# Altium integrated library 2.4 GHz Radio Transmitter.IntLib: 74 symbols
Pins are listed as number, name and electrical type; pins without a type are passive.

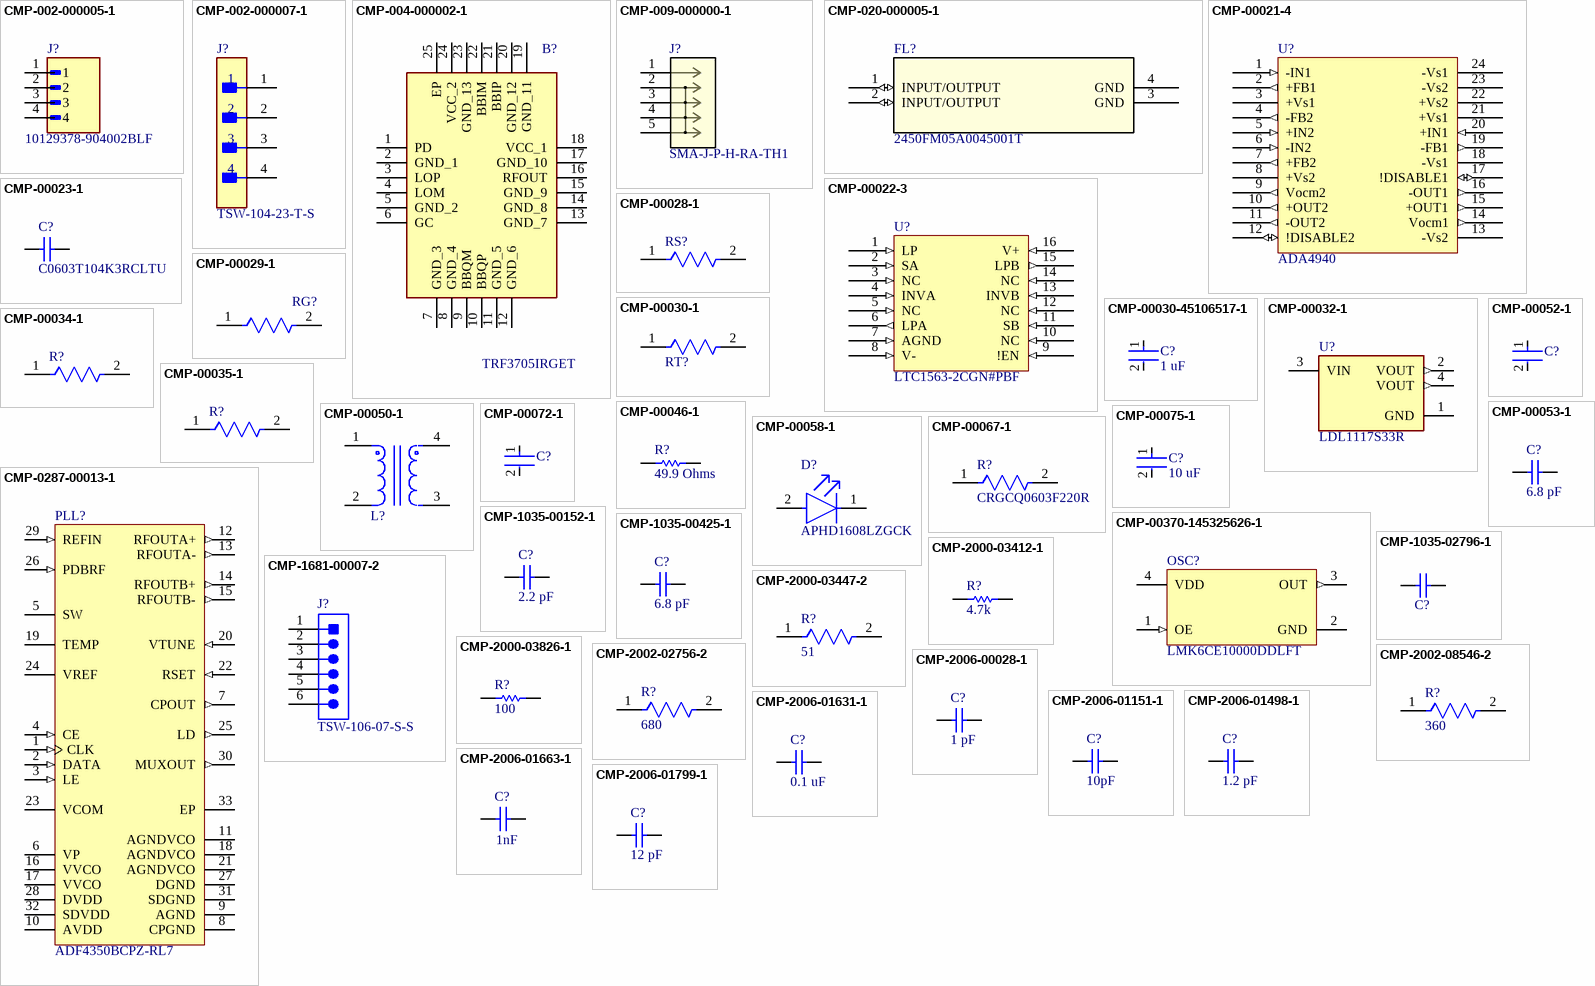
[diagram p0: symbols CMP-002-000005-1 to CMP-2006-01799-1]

## CMP-002-000005-1
designator J?, comment 10129378-904002BLF
EconoStikâ„¢ 2.54mm, Board to Board Connector, Unshrouded Verticl Header, Through Hole, Single Row, 4 Positions, 2.54 mm (0.100in) Pitch.; MF: Amphenol ICC (FCI)
footprint AMPHENOL_10129378-904002BLF
pins: 1, 2, 3, 4

## CMP-002-000007-1
designator J?, comment TSW-104-23-T-S
Pin Header, Board-to-Board, 2.54 mm, 1 Rows, 4 Contacts, Through Hole, TSW Series
footprint FP-TSW-104-23-T-S-MFG
pins: 1, 2, 3, 4

## CMP-004-000002-1
designator B?, comment TRF3705IRGET
TRF3705IRGET, Modulator Quadrature 3.1dB 3.15  3.6 V 24-Pin VQFN; Manufacturer_Name: Texas Instruments; Geometry.Height: 1mm
footprint QFN50P400X400X100-25N-D
pins: 1 PD, 2 GND_1, 3 LOP, 4 LOM, 5 GND_2, 6 GC, 7 GND_3, 8 GND_4, 9 BBQM, 10 BBQP, 11 GND_5, 12 GND_6, 13 GND_7, 14 GND_8, 15 GND_9, 16 RFOUT, 17 GND_10, 18 VCC_1, 19 GND_11, 20 GND_12, 21 BBIP, 22 BBIM, 23 GND_13, 24 VCC_2, 25 EP

## CMP-009-000000-1
designator J?, comment SMA-J-P-H-RA-TH1
Description; Manufacturer_Name: Samtec Inc
footprint CONN_SMA-J-P-H-RA-TH1_SAI
pins: 1, 2, 3, 4, 5

## CMP-020-000005-1
designator FL?, comment 2450FM05A0045001T
Description; Manufacturer_Name: Johanson Technology
footprint 2450FM05_JOT
pins: 1 INPUT/OUTPUT (io), 2 INPUT/OUTPUT (io), 3 GND (power), 4 GND (power)

## CMP-00021-4
designator U?, comment ADA4940
ROHS3Compliant EAR99 ADA4940 Tape & Reel (TR) op amp amplifier circuit 3mm 1.1muA 60muV 90dB
footprint ADA4940-Footprint-1
pins: 1 -IN1 (in), 2 +FB1 (out), 3 +Vs1 (power), 4 -FB2 (out), 5 +IN2 (in), 6 -IN2 (in), 7 +FB2 (out), 8 +Vs2 (power), 9 Vocm2 (out), 10 +OUT2 (out), 11 -OUT2 (out), 12 !DISABLE2 (io), 13 -Vs2 (power), 14 Vocm1 (out), 15 +OUT1 (out), 16 -OUT1 (out), 17 !DISABLE1 (io), 18 -Vs1 (power), 19 -FB1 (out), 20 +IN1 (in), 21 +Vs1 (power), 22 +Vs2 (power), 23 -Vs2 (power), 24 -Vs1 (power)

## CMP-00022-3
designator U?, comment LTC1563-2CGN#PBF
Active Filter Dual Low Pass 8th Order 256kHz 16-Pin SSOP N
footprint LTC1563-2CGN#PBF-Footprint-1
pins: 1 LP (in), 2 SA (in), 3 NC (in), 4 INVA (in), 5 NC (in), 6 LPA (out), 7 AGND (in), 8 V- (in), 9 !EN (in), 10 NC (in), 11 SB (in), 12 NC (in), 13 INVB (in), 14 NC (in), 15 LPB (out), 16 V+ (in)

## CMP-00023-1
designator C?, comment C0603T104K3RCLTU
Ceramic Capacitor, Multilayer, Ceramic, 25V, 10% +Tol, 10% -Tol, X7R, 15% TC, 0.1uF, Surface Mount, 0603
footprint CAPC1608X87X35LL15T15 (Chip Capacitor, 2-Leads, Body 1.60x0.80mm, IPC High Density)
footprint CAPC1608X87X35ML15T15 (Chip Capacitor, 2-Leads, Body 1.60x0.80mm, IPC Low Density)
footprint CAPC1608X87X35NL15T15 (Chip Capacitor, 2-Leads, Body 1.60x0.80mm, IPC Medium Density)
pins: 1, 2
1 alternate drawing of the same symbol

## CMP-00028-1
designator RS?, comment CRCW060350R0FKEA  (value not drawn)
Res Thick Film 0603 50 Ohm 1% 0.1W(1/10W) ±100ppm/C Pad SMD Automotive T/R
footprint FP-CRCW0603-e3-IPC_C
footprint FP-CRCW0603-e3-IPC_B
footprint FP-CRCW0603-e3-IPC_A
footprint FP-CRCW0603-e3-MFG
pins: 1, 2

## CMP-00029-1
designator RG?, comment 6-1879336-2  (value not drawn)
Fixed Resistor, Thin Film, 0.063W, 1000ohm, 50V, 1% +/-Tol, 50ppm/Cel, Surface Mount, 0603
footprint FP-CPF0603-MFG
footprint FP-CPF0603-IPC_A
footprint FP-CPF0603-IPC_B
footprint FP-CPF0603-IPC_C
pins: 1, 2

## CMP-00030-1
designator RT?, comment CR0603-FX-52R3ELF  (value not drawn)
Resistor, thick film, SMD 0603 (1608), 52.3 Ω, 0.1 W, ±1 %, CR0603-FX-52R3ELF
footprint FP-CR0603-IPC_A
footprint FP-CR0603-IPC_B
footprint FP-CR0603-MFG
footprint FP-CR0603-IPC_C
pins: 1, 2

## CMP-00030-45106517-1
designator C?, comment 1 uF
VJ0603Y105KXJCW1BC Multilayer Ceramic Capacitor, 1 uF, 16 V, ± 10%, X7R, 0603 [1608 Metric]; NexarPartId: 45106517; Capacitance: 1µF; Voltage Rating: 16V; Dielectric Material: Tantalum
footprint FP-VJ0603Y105KXJCW1BC-MFG (Multilayer Ceramic Capacitor, 1 uF, 16 V, ± 10%, X7R, 0603 [1608 Metric])
footprint FP-VJ0603Y105KXJCW1BC-IPC_A (Multilayer Ceramic Capacitor, 1 uF, 16 V, ± 10%, X7R, 0603 [1608 Metric])
footprint FP-VJ0603Y105KXJCW1BC-IPC_B (Multilayer Ceramic Capacitor, 1 uF, 16 V, ± 10%, X7R, 0603 [1608 Metric])
footprint FP-VJ0603Y105KXJCW1BC-IPC_C (Multilayer Ceramic Capacitor, 1 uF, 16 V, ± 10%, X7R, 0603 [1608 Metric])
pins: 1, 2

## CMP-00032-1
designator U?, comment LDL1117S33R
LDL1117 Series 1.2 A 3.3 V High PSRR LDO Linear Voltage Regulator-SOT-223
footprint FP-SOT223-0046067-IPC_A
footprint FP-SOT223-0046067-IPC_B
footprint FP-SOT223-0046067-IPC_C
pins: 1 GND (power), 2 VOUT (out), 3 VIN (power), 4 VOUT (out)

## CMP-00034-1
designator R?, comment CPF0603B120KE1  (value not drawn)
Res Thin Film 0603 120K Ohm 0.1% 1/16W ±25ppm/°C Molded SMD SMD Paper T/R
footprint FP-CPF0603-MFG
footprint FP-CPF0603-IPC_A
footprint FP-CPF0603-IPC_B
footprint FP-CPF0603-IPC_C
pins: 1, 2

## CMP-00035-1
designator R?, comment CRGCQ0603F22R  (value not drawn)
Res Thick Film 0603 22 Ohm 1% 0.1W(1/10W) ±200ppm/C Pad SMD Automotive T/R
footprint FP-CRGCQ0603-IPC_A
footprint FP-CRGCQ0603-IPC_C
footprint FP-CRGCQ0603-IPC_B
pins: 1, 2

## CMP-00046-1
designator R?, comment 49.9 Ohms
Res Thin Film 0603 49.9 Ohm 0.1% 1/8W ±25ppm/°C Molded SMD SMD Paper T/R; Power Rating: 125mW; Working Voltage: 75V; Max Power Dissipation: 100mW; Value: 49.9Ω; Voltage Rating (DC): 50V
footprint RESC1609X55X30NL10T20 (Chip Resistor, 2-Leads, Body 1.60x0.85mm, IPC Medium Density)
footprint RESC1609X55X30ML10T20 (Chip Resistor, 2-Leads, Body 1.60x0.85mm, IPC Low Density)
footprint RESC1609X55X30LL10T20 (Chip Resistor, 2-Leads, Body 1.60x0.85mm, IPC High Density)
pins: 1, 2
1 alternate drawing of the same symbol

## CMP-00050-1
designator L?, comment DLW5BSM501TQ2L  (value not drawn)
Common Mode Chokes Dual 500Ohm 100MHz 1A 0.23Ohm DCR SMD T/R; Tolerance: 40%; Core Material: Ferrite; Value: 500Ω; Impedance: 2.8kΩ; DC Resistance (DCR): 230mΩ; Insulation Resistance: 10MΩ; Number of Circuits: 2; Voltage Rating: 50V
footprint FP-DLW5BS-MFG
pins: 1, 2, 3, 4

## CMP-00052-1
designator C?, comment CGA5L2C0G1H104J160AA  (value not drawn)
CGA Series 1206 100 nF 50 V ±5 % Tolerance C0G SMT Multilayer Ceramic Capacitor
footprint FP-CGA5L-MFG
footprint FP-CGA5L-IPC_B
footprint FP-CGA5L-IPC_C
footprint FP-CGA5L-IPC_A
pins: 1, 2

## CMP-00053-1
designator C?, comment 6.8 pF
6.8pF 0603 C0G Multilayer Ceramic Capacitors MLCC - SMD/SMT 16volts +/-0.5pF; Voltage Rating (DC): 16V
footprint CAPC0603(1608)100_N (Chip Capacitor, Body 1.6x0.8mm, Height 1.0mm, IPC Medium Density)
footprint CAPC0603(1608)100_L (Chip Capacitor, Body 1.6x0.8mm, Height 1.0mm, IPC High Density)
footprint CAPC0603(1608)100_M (Chip Capacitor, Body 1.6x0.8mm, Height 1.0mm, IPC Low Density)
pins: 1, 2
1 alternate drawing of the same symbol

## CMP-00058-1
designator D?, comment APHD1608LZGCK
Standard LEDs; SMD 0608 Compact Dome Lens LED; 1.6x0.8 mm; Green; (Cut Reel)
footprint FP-APHD1608LZGCK-MFG
pins: 1 C, 2 A

## CMP-00067-1
designator R?, comment CRGCQ0603F220R
Res Thick Film 0603 220 Ohm 1% 0.1W(1/10W) ±100ppm/C Pad SMD T/R Automotive
footprint FP-CRGCQ0603-IPC_A
footprint FP-CRGCQ0603-IPC_C
footprint FP-CRGCQ0603-IPC_B
pins: 1, 2

## CMP-00072-1
designator C?, comment GRM21BZ71H475ME15K  (value not drawn)
Cap, Mlcc, 4.7Uf, X7R, 50V, 0805 Rohs Compliant: Yes
footprint FP-GRM21B-0_2-e0_2_0_7-IPC_A
footprint FP-GRM21B-0_2-e0_2_0_7-MFG
footprint FP-GRM21B-0_2-e0_2_0_7-IPC_C
footprint FP-GRM21B-0_2-e0_2_0_7-IPC_B
pins: 1, 2

## CMP-00075-1
designator C?, comment 10 uF
0805 10 uF 6.3 V ±10% Tolerance X7R Multilayer Ceramic Chip Capacitor; Manufacturer Lifecycle Status: IN PRODUCTION; Voltage Rating: 6.3V; Value: 10µF
footprint FP-GCM21B-0_15-IPC_A
footprint FP-GCM21B-0_15-IPC_C
footprint FP-GCM21B-0_15-MFG
footprint FP-GCM21B-0_15-IPC_B
pins: 1, 2

## CMP-0287-00013-1
designator PLL?, comment ADF4350BCPZ-RL7
Wideband Synthesizer with Integrated VCO, CP-32-2, Pb-Free, 1500 Reel; RF Prescalers: 4/5, 8/9; Single/Dual: Single; Max RF Input (MHz): 4.4GHz; Supply Current: 110mA; Frequency Range: 137.5MHz-4.35GHz; Max REFin (MHz): 250MHz; Norm Phase Noise (dBc/Hz): -220dBc
footprint ADI-CP-32-2_L (QFN, 32-Leads, Body 5x5mm, Pitch 0.5mm, Thermal Pad 3.1x3.1mm, IPC High Density)
footprint ADI-CP-32-2_M (QFN, 32-Leads, Body 5x5mm, Pitch 0.5mm, Thermal Pad 3.1x3.1mm, IPC Low Density)
footprint ADI-CP-32-2_N (QFN, 32-Leads, Body 5x5mm, Pitch 0.5mm, Thermal Pad 3.1x3.1mm, IPC Medium Density)
pins: 1 CLK (in) "Serial Clock Input. Data is clocked into the 32-bit shift register on the CLK rising edge. This input is a high impedance CMOS input.", 2 DATA (in) "Serial Data Input. The serial data is loaded MSB first with the three LSBs as the control bits. This input is a high impedance CMOS input.", 3 LE (in) "Load Enable, CMOS Input. When LE goes high, the data stored in the shift register is loaded into the register that is selected by the three LSBs.", 4 CE (in) "Chip Enable. A logic low on this pin powers down the device and puts the charge pump into three-state mode. [see datasheet]", 5 SW "Fast-Lock Switch. A connection should be made from the loop filter to this pin when using the fast-lock mode.", 6 VP (power) "Charge Pump Power Supply. This pin is to be equal to AVDD. Decoupling capacitors to the ground plane are to be placed as close as possible to this pin.", 7 CPOUT (out) "Charge Pump Output. When enabled, this provides +/-ICP to the external loop filter. The output of the loop filter is connected to VTUNE to drive the internal VCO.", 8 CPGND (power) "Charge Pump Ground. This is the ground return pin for CPOUT.", 9 AGND (power) "Analog Ground. This is a ground return pin for AVDD.", 10 AVDD (power) "Analog Power Supply. This pin ranges from 3.0 V to 3.6 V. Decoupling capacitors to the analog ground plane are to be placed as close as possible to this pin. [see datasheet]", 11 AGNDVCO (power) "VCO Analog Ground. These are the ground return pins for the VCO.", 12 RFOUTA+ (out) "VCO Output. The output level is programmable. The VCO fundamental output or a divided down version is available.", 13 RFOUTA- (out) "Complementary VCO Output. The output level is programmable. The VCO fundamental output or a divided down version is available.", 14 RFOUTB+ (out) "Auxilliary VCO Output. The output level is programmable. The VCO fundamental output or a divided down version is available.", 15 RFOUTB- (out) "Complementary Auxilliary VCO Output. The output level is programmable. The VCO fundamental output or a divided down version is available.", 16 VVCO (power) "Power Supply for the VCO. This ranges from 3.0 V to 3.6 V. Decoupling capacitors to the analog ground plane should be placed as close as possible to these pins. [see datasheet]", 17 VVCO (power) "Power Supply for the VCO. This ranges from 3.0 V to 3.6 V. Decoupling capacitors to the analog ground plane should be placed as close as possible to these pins. [see datasheet]", 18 AGNDVCO (power) "VCO Analog Ground. These are the ground return pins for the VCO.", 19 TEMP "Temperature Compensation Output. Decoupling capacitors to the ground plane are to be placed as close as possible to this pin.", 20 VTUNE (in) "Control Input to the VCO. This voltage determines the output frequency and is derived from filtering the CPOUT output voltage.", 21 AGNDVCO (power) "VCO Analog Ground. These are the ground return pins for the VCO.", 22 RSET (in) "Connecting a resistor between this pin and GND sets the charge pump output current. The nominal voltage bias at the RSET pin is 0.55 V. [see datasheet.]", 23 VCOM "Internal Compensation Node Biased at Half the Tuning Range. Decoupling capacitors to the ground plane should be placed as close as possible to this pin.", 24 VREF "Reference Voltage. Decoupling capacitors to the ground plane should be placed as close as possible to this pin.", 25 LD (out) "Lock Detect Output Pin. This pin outputs a logic high to indicate PLL lock. A logic low output indicates loss of PLL lock.", 26 PDBRF (in) "RF Power-Down. A logic low on this pin mutes the RF outputs. This function is also software controllable.", 27 DGND (power) "Digital Ground. Ground return path for DVDD.", 28 DVDD (power) "Digital Power Supply. This pin should be the same voltage as AVDD. Decoupling capacitors to the ground plane should be placed as close as possible to this pin.", 29 REFIN (in) "Reference Input. This is a CMOS input with a nominal threshold of VDD/2 and a dc equivalent input resistance of 100 k ohm. [see datasheet]", 30 MUXOUT (out) "Multiplexer Output. This multiplexer output allows either the lock detect, the scaled RF, or the scaled reference frequency to be accessed externally.", 31 SDGND (power) "Digital Sigma-Delta (Sigma-Delta) Modulator Ground. Ground return path for the Sigma-Delta modulator.", 32 SDVDD (power) "Power Supply Pin for the Digital Sigma-Delta Modulator. Should be the same voltage as AVDD. Decouplingcapacitorsto the ground plane are to be placed as close as possible to this pin.", 33 EP (power) "Exposed Pad."

## CMP-00370-145325626-1
designator OSC?, comment LMK6CE10000DDLFT
IC 100 MHz LVCMOS Oscillator 1.8V Enable/Disable 4-VDFN; Manufacturer Lifecycle Status: ACTIVE; Frequency: 100MHz; Load Capacitance: 15pF; Max Supply Current: 44mA; Max Junction Temperature (Tj): 125°C; Max Supply Voltage: 1.9V; Min Supply Voltage: 1.7V
footprint DLF0004A_MFG (Recommended Land Pattern)
footprint DFN250X200X100-4_DLF0004A_L
footprint DFN250X200X100-4_DLF0004A_M
footprint DFN250X200X100-4_DLF0004A_N
pins: 1 OE (in), 2 GND (power), 3 OUT (out), 4 VDD (power)

## CMP-1035-00152-1
designator C?, comment 2.2 pF
CAP 2.2pF 16V ±0.5pF 0603 (1608 Metric) Thickness 1mm SMD; Case-EIA: 0603; Tolerance: Â±0.5pF; Case-Metric: 1608
footprint CAPC0603(1608)100_N (Chip Capacitor, Body 1.6x0.8mm, Height 1.0mm, IPC Medium Density)
footprint CAPC0603(1608)100_M (Chip Capacitor, Body 1.6x0.8mm, Height 1.0mm, IPC Low Density)
footprint CAPC0603(1608)100_L (Chip Capacitor, Body 1.6x0.8mm, Height 1.0mm, IPC High Density)
pins: 1, 2
1 alternate drawing of the same symbol

## CMP-1035-00425-1
designator C?, comment 6.8 pF
CAP 6.8pF 16V ±0.5pF 0603 (1608 Metric) Thickness 1mm SMD; Case-Metric: 1608; Tolerance: Â±0.5pF; Case-EIA: 0603
footprint CAPC0603(1608)100_L (Chip Capacitor, Body 1.6x0.8mm, Height 1.0mm, IPC High Density)
footprint CAPC0603(1608)100_N (Chip Capacitor, Body 1.6x0.8mm, Height 1.0mm, IPC Medium Density)
footprint CAPC0603(1608)100_M (Chip Capacitor, Body 1.6x0.8mm, Height 1.0mm, IPC Low Density)
pins: 1, 2
1 alternate drawing of the same symbol

## CMP-1035-02796-1
designator C?, comment CAP 10uF 6.3V 0603(1608)  (value not drawn)
CAP 10uF 6.3V ±10% 0603 (1608 Metric) Thickness 1mm SMD; Case-EIA: 0603; Tolerance: Â±10%; Case-Metric: 1608
footprint CAPC0603(1608)100_M (Chip Capacitor, Body 1.6x0.8mm, Height 1.0mm, IPC Low Density)
footprint CAPC0603(1608)100_N (Chip Capacitor, Body 1.6x0.8mm, Height 1.0mm, IPC Medium Density)
footprint CAPC0603(1608)100_L (Chip Capacitor, Body 1.6x0.8mm, Height 1.0mm, IPC High Density)
pins: 1, 2
1 alternate drawing of the same symbol

## CMP-1681-00007-2
designator J?, comment TSW-106-07-S-S
Male Header, Pitch 2.54 mm, 1 x 6 Position, Height 8.38 mm, Tail Length 2.54 mm, -55 to 125 degC, RoHS, Bulk; Manufacturer: Samtec; Rows: 1
footprint SMTC-TSW-106-07-S-S_V (Header, 6-Leads, Body 15.24x2.54mm, Pitch 2.54mm)
pins: 1, 2, 3, 4, 5, 6

## CMP-2000-03412-1
designator R?, comment 4.7k
Manufacturer: Vishay Dale; Part Number: CRCW06034K70FKTA
footprint RESC1609X50X30NL10T20 (Chip Resistor, 2-Leads, Body 1.55x0.85mm, IPC Medium Density)
footprint RESC1609X50X30ML10T20 (Chip Resistor, 2-Leads, Body 1.55x0.85mm, IPC Low Density)
footprint RESC1609X50X30LL10T20 (Chip Resistor, 2-Leads, Body 1.55x0.85mm, IPC High Density)
pins: 1, 2
1 alternate drawing of the same symbol

## CMP-2000-03447-2
designator R?, comment 51
RES Thick Film, 51Ω, 5%, 0.1W, 200ppm/°C, 0603; Max Power Dissipation: 100mW; Working Voltage: 75V; Resistance: 51R
footprint FP-CRCW0603-e3-IPC_B
footprint FP-CRCW0603-e3-MFG
footprint FP-CRCW0603-e3-IPC_A
footprint FP-CRCW0603-e3-IPC_C
pins: 1, 2

## CMP-2000-03826-1
designator R?, comment 100
Manufacturer: Vishay Dale; Part Number: CRCW0603100RFKTA
footprint RESC1609X50X30LL10T20 (Chip Resistor, 2-Leads, Body 1.55x0.85mm, IPC High Density)
footprint RESC1609X50X30ML10T20 (Chip Resistor, 2-Leads, Body 1.55x0.85mm, IPC Low Density)
footprint RESC1609X50X30NL10T20 (Chip Resistor, 2-Leads, Body 1.55x0.85mm, IPC Medium Density)
pins: 1, 2
1 alternate drawing of the same symbol

## CMP-2002-02756-2
designator R?, comment 680
RES SMD 680 OHM 0.1% 1/16W 0402; Manufacturer: Yageo; Manufacturer Part Number: RT0402BRD07680RL; Resistance: 680Ω; Value: 680Ω; Power Rating: 0.063W; Tolerance: 0.001; Temperature Coefficient: 25 ppm/°C; Voltage Rating: 50V
footprint FP-RT0402-MFG
footprint FP-RT0402-IPC_C
footprint FP-RT0402-IPC_B
footprint FP-RT0402-IPC_A
pins: 1, 2

## CMP-2002-08546-2
designator R?, comment 360
RES Thick Film, 360Ω, 1%, 0.063W, 100ppm/°C, 0402; Voltage Rating: 50V; Max Power Dissipation: 63mW; Resistance: 360R
footprint FP-CRCW0402-e3-IPC_C
footprint FP-CRCW0402-e3-MFG
footprint FP-CRCW0402-e3-IPC_B
footprint FP-CRCW0402-e3-IPC_A
pins: 1, 2

## CMP-2006-00028-1
designator C?, comment 1 pF
Manufacturer: Vitramon; Part Number: VJ0603A1R0CXACW1BC
footprint CAPC1608X95X40LL15T15 (Chip Capacitor, 2-Leads, Body 1.60x0.80mm, IPC High Density)
footprint CAPC1608X95X40NL15T15 (Chip Capacitor, 2-Leads, Body 1.60x0.80mm, IPC Medium Density)
footprint CAPC1608X95X40ML15T15 (Chip Capacitor, 2-Leads, Body 1.60x0.80mm, IPC Low Density)
pins: 1, 2
1 alternate drawing of the same symbol

## CMP-2006-01151-1
designator C?, comment 10pF
Manufacturer: Vitramon; Part Number: VJ0603A100JXBAC
footprint CAPC1608X92X38LL15T08 (Chip Capacitor, 2-Leads, Body 1.60x0.80mm, IPC High Density)
footprint CAPC1608X92X38ML15T08 (Chip Capacitor, 2-Leads, Body 1.60x0.80mm, IPC Low Density)
footprint CAPC1608X92X38NL15T08 (Chip Capacitor, 2-Leads, Body 1.60x0.80mm, IPC Medium Density)
pins: 1, 2
1 alternate drawing of the same symbol

## CMP-2006-01498-1
designator C?, comment 1.2 pF
Part Number: VJ0603D1R2BXPAJ; Manufacturer: Vitramon
footprint CAPC1608X92X38NL15T08 (Chip Capacitor, 2-Leads, Body 1.60x0.80mm, IPC Medium Density)
footprint CAPC1608X92X38ML15T08 (Chip Capacitor, 2-Leads, Body 1.60x0.80mm, IPC Low Density)
footprint CAPC1608X92X38LL15T08 (Chip Capacitor, 2-Leads, Body 1.60x0.80mm, IPC High Density)
pins: 1, 2
1 alternate drawing of the same symbol

## CMP-2006-01631-1
designator C?, comment 0.1 uF
Ceramic Capacitor, Multilayer, Ceramic, 16V, 20% +Tol, 20% -Tol, X7R, 15% TC, 0.1uF, Surface Mount, 0603; Part Number: VJ0603Y104MXJPW1BC; Manufacturer: Vitramon
footprint CAPC1608X95X40LL15T15 (Chip Capacitor, 2-Leads, Body 1.60x0.80mm, IPC High Density)
footprint CAPC1608X95X40ML15T15 (Chip Capacitor, 2-Leads, Body 1.60x0.80mm, IPC Low Density)
footprint CAPC1608X95X40NL15T15 (Chip Capacitor, 2-Leads, Body 1.60x0.80mm, IPC Medium Density)
pins: 1, 2
1 alternate drawing of the same symbol

## CMP-2006-01663-1
designator C?, comment 1nF
Manufacturer: Vitramon; Part Number: VJ0603A102JXXCW1BC
footprint CAPC1608X95X40NL15T15 (Chip Capacitor, 2-Leads, Body 1.60x0.80mm, IPC Medium Density)
footprint CAPC1608X95X40ML15T15 (Chip Capacitor, 2-Leads, Body 1.60x0.80mm, IPC Low Density)
footprint CAPC1608X95X40LL15T15 (Chip Capacitor, 2-Leads, Body 1.60x0.80mm, IPC High Density)
pins: 1, 2
1 alternate drawing of the same symbol

## CMP-2006-01799-1
designator C?, comment 12 pF
Manufacturer: Vitramon; Part Number: VJ0603A120KXJCW1BC
footprint CAPC1608X95X40ML15T15 (Chip Capacitor, 2-Leads, Body 1.60x0.80mm, IPC Low Density)
footprint CAPC1608X95X40NL15T15 (Chip Capacitor, 2-Leads, Body 1.60x0.80mm, IPC Medium Density)
footprint CAPC1608X95X40LL15T15 (Chip Capacitor, 2-Leads, Body 1.60x0.80mm, IPC High Density)
pins: 1, 2
1 alternate drawing of the same symbol

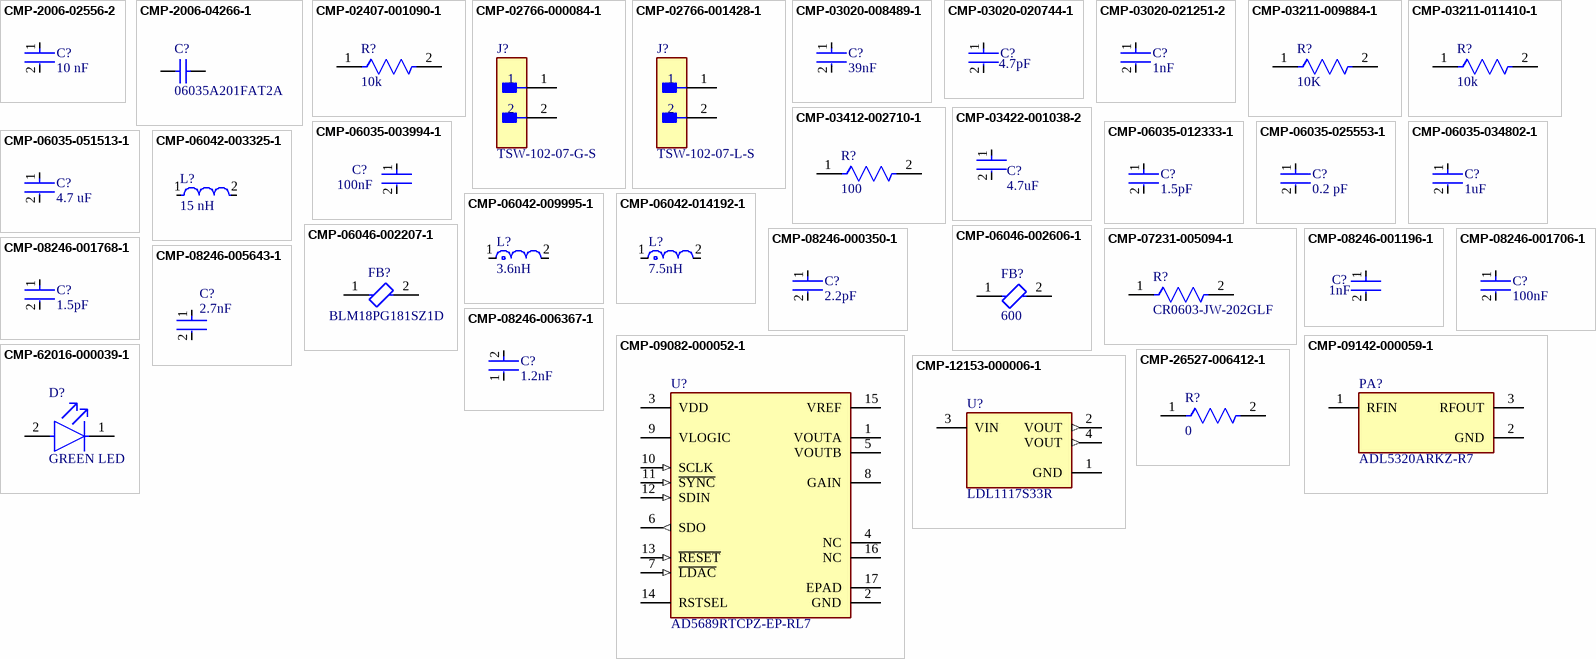
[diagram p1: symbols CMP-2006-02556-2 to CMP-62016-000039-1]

## CMP-2006-02556-2
designator C?, comment 10 nF
Chip Multilayer Ceramic Capacitors for General Purpose, 0603, 10000pF, C0G, 30ppm/°C, 5%, 50V; Capacitance: 10nF
footprint FP-GRM188-0_1-e0_2_0_5-IPC_B
footprint FP-GRM188-0_1-e0_2_0_5-IPC_C
footprint FP-GRM188-0_1-e0_2_0_5-IPC_A
footprint FP-GRM188-0_1-e0_2_0_5-MFG
pins: 1, 2

## CMP-2006-04266-1
designator C?, comment 06035A201FAT2A
200pF; Manufacturer: AVX Interconnect / Elco
footprint CAPC1608X90X35LL15T15 (Chip Capacitor, 2-Leads, Body 1.60x0.81mm, IPC High Density)
footprint CAPC1608X90X35ML15T15 (Chip Capacitor, 2-Leads, Body 1.60x0.81mm, IPC Low Density)
footprint CAPC1608X90X35NL15T15 (Chip Capacitor, 2-Leads, Body 1.60x0.81mm, IPC Medium Density)
pins: 1, 2
1 alternate drawing of the same symbol

## CMP-02407-001090-1
designator R?, comment 10k
RES SMD 100 OHM 1% 1/8W 0603
footprint FP-MCT0603-IPC_B
footprint FP-MCT0603-IPC_A
footprint FP-MCT0603-MFG
footprint FP-MCT0603-IPC_C
pins: 1, 2

## CMP-02766-000084-1
designator J?, comment TSW-102-07-G-S
CONN HEADER VERT 2POS 2.54MM; Manufacturer: Samtec; Number Of Contacts: 2; Voltage Rating: 550V; Conn Orientation: Straight; Current Rating: 6.3A; Conn Gender: Male
footprint FP-TSW-102-07-G-S-MFG
pins: 1, 2

## CMP-02766-001428-1
designator J?, comment TSW-102-07-L-S
CONN HEADER VERT 2POS 2.54MM; Voltage Rating: 550V; Current Rating: 7.6A; Gender: Male; Number of Contacts: 2; Connector Type: Male Pin
footprint FP-TSW-102-07-L-S-MFG
pins: 1, 2

## CMP-03020-008489-1
designator C?, comment 39nF
C1206 39,000 pF C0G 5.00% 50 V; Manufacturer Part Number: C1206C393J5GACTU; Manufacturer: KEMET; Temperature Coefficient: 15%; Material: Ceramic; Automotive Grade: Grade 0; Voltage Rating: 50 V; Tolerance: 0.05
footprint FP-C1206C-EB-MFG
footprint FP-C1206C-EB-IPC_C
footprint FP-C1206C-EB-IPC_B
footprint FP-C1206C-EB-IPC_A
pins: 1, 2

## CMP-03020-020744-1
designator C?, comment 4.7pF
C0603 4.7 pF C0G 30ppm/°C 0.25 pF 50 V; Manufacturer Part Number: C0603C479C5GACAUTO; Manufacturer: KEMET; Tolerance: 0.25 pF; Voltage Rating: 50 V; Automotive Grade: Grade 1; Material: Ceramic
footprint FP-C0603C-CF-MFG
footprint FP-C0603C-CF-IPC_C
footprint FP-C0603C-CF-IPC_B
footprint FP-C0603C-CF-IPC_A
pins: 1, 2

## CMP-03020-021251-2
designator C?, comment 1nF
CAP CER 1000PF 16V X7R 0402; Dielectric Material: Ceramic; Tolerance: 10%
footprint FP-C0402C102K4RAC7411-MFG
footprint FP-C0402C102K4RAC7411-IPC_C
footprint FP-C0402C102K4RAC7411-IPC_B
footprint FP-C0402C102K4RAC7411-IPC_A
pins: 1, 2

## CMP-03211-009884-1
designator R?, comment 10K
CRGCQ 0603 10K 5%; Manufacturer Part Number: CRGCQ0603J10K; Manufacturer: TE Connectivity; Tolerance: 0.05; Power Rating: 0.1W; Resistance: 10KΩ; Voltage Rating: 75V; Value: 10KΩ; Temperature Coefficient: ±100ppm/°C
footprint FP-CRGCQ0603-IPC_C
footprint FP-CRGCQ0603-IPC_B
footprint FP-CRGCQ0603-IPC_A
pins: 1, 2

## CMP-03211-011410-1
designator R?, comment 10k
RES SMD 10K OHM 1% 1/16W 0402; Resistance: 10kR; Voltage Rating (DC): 50V; Temperature Coefficient: 100ppm/°C; Max Power Dissipation: 63mW; Number of Resistors: 1
footprint FP-CRG0402-IPC_B
footprint FP-CRG0402-IPC_C
footprint FP-CRG0402-IPC_A
pins: 1, 2

## CMP-03412-002710-1
designator R?, comment 100
RES SMD 0603 1/4W 1% 100 OHM; Manufacturer Part Number: SR0603FR-7T100RL; Manufacturer: Yageo; Power Rating: 0.25W; Voltage Rating: 75V; Automotive Grade: Grade 0; Resistance: 100Ω; Tolerance: 0.01; Value: 100Ω
footprint FP-SR0603-MFG
footprint FP-SR0603-IPC_C
footprint FP-SR0603-IPC_B
footprint FP-SR0603-IPC_A
pins: 1, 2

## CMP-03422-001038-2
designator C?, comment 4.7uF
CAP CER 4.7UF 6.3V X7R 0603; Tolerance: 20%
footprint FP-CC0603-DC-MFG
footprint FP-CC0603-DC-IPC_C
footprint FP-CC0603-DC-IPC_B
footprint FP-CC0603-DC-IPC_A
pins: 1, 2

## CMP-06035-003994-1
designator C?, comment 100nF
Chip Multilayer Ceramic Capacitors for General Purpose, 1206, 0.10uF, C0G, 30ppm/°C, 5%, 50V
footprint FP-GRM31C-0_2-e0_3_0_8-IPC_B
footprint FP-GRM31C-0_2-e0_3_0_8-MFG
footprint FP-GRM31C-0_2-e0_3_0_8-IPC_A
footprint FP-GRM31C-0_2-e0_3_0_8-IPC_C
pins: 1, 2

## CMP-06035-012333-1
designator C?, comment 1.5pF
Ceramic Capacitor for Automotive 1.5pF ±5% 50VDC C0G 0402 Paper T/R; Voltage Rating: 50V
footprint FP-GCM155-0_05-IPC_A
footprint FP-GCM155-0_05-IPC_B
footprint FP-GCM155-0_05-IPC_C
footprint FP-GCM155-0_05-MFG
pins: 1, 2

## CMP-06035-025553-1
designator C?, comment 0.2 pF
Ceramic Capacitor 0.2pF ±0.1pF 250VDC C0G 0603 Paper T/R; Voltage Rating: 250V
footprint FP-GQM187-0_15-IPC_C
footprint FP-GQM187-0_15-IPC_B
footprint FP-GQM187-0_15-IPC_A
footprint FP-GQM187-0_15-MFG
pins: 1, 2

## CMP-06035-034802-1
designator C?, comment 1uF
Multi-Layer Ceramic Capacitor 1uF 6.3V X7R ±10% 0402 Paper T/R
footprint FP-GRT155-0_05-IPC_C
footprint FP-GRT155-0_05-IPC_B
footprint FP-GRT155-0_05-MFG
footprint FP-GRT155-0_05-IPC_A
pins: 1, 2

## CMP-06035-051513-1
designator C?, comment 4.7 uF
Multilayer Ceramic Capacitors MLCC - SMD/SMT 0805 4.7uF 10%, 16VDC,  X7R 15%; Voltage Rating (DC): 16V
footprint FP-GCJ21B-0_3-IPC_A
footprint FP-GCJ21B-0_3-IPC_B
footprint FP-GCJ21B-0_3-IPC_C
footprint FP-GCJ21B-0_3-MFG
pins: 1, 2

## CMP-06042-003325-1
designator L?, comment 15 nH
Wire Wound Ferrite type RF Inductor 15nH ±5% 2200mA 0.025Ω 0603 (1608); Test Frequency: 10MHz; DC Resistance (DCR): 25mR; Self Resonant Frequency: 2GHz; Current Rating: 2.2A; Shielding: Unshielded
footprint FP-LQW18CA_00-MFG
pins: 1, 2

## CMP-06042-009995-1
designator L?, comment 3.6nH
Multilayer type RF Inductor 3.6nH ±0.2nH 0.14Ω 750mA 0402; Core Material: Air; Self Resonant Frequency: 6GHz; Shielding: Unshielded; Test Frequency: 100MHz; DC Resistance (DCR): 140mR
footprint FP-LQG15HH_02-MFG
footprint FP-LQG15HH_02-IPC_A
footprint FP-LQG15HH_02-IPC_B
footprint FP-LQG15HH_02-IPC_C
pins: 1, 2

## CMP-06042-014192-1
designator L?, comment 7.5nH
Multilayer type Inductor for Automotive 7.5nH ±3% 0.16Ω 600mA 0402; Shielding: Unshielded; Test Frequency: 100MHz; Core Material: Air; DC Resistance (DCR): 160mR; Self Resonant Frequency: 4GHz
footprint FP-LQG15WH_02-MFG
footprint FP-LQG15WH_02-IPC_C
footprint FP-LQG15WH_02-IPC_A
footprint FP-LQG15WH_02-IPC_B
pins: 1, 2

## CMP-06046-002207-1
designator FB?, comment BLM18PG181SZ1D
Chip Ferrite Bead, 0603, 180Ω @ 100MHz, 0.09Ω, 25%, 1.5A
footprint FP-BLM18-0_15-t0_8-IPC_B
footprint FP-BLM18-0_15-t0_8-IPC_C
footprint FP-BLM18-0_15-t0_8-MFG
footprint FP-BLM18-0_15-t0_8-IPC_A
pins: 1, 2

## CMP-06046-002606-1
designator FB?, comment 600
Chip Ferrite Bead, 0805, 60Ω @ 100MHz, 0.02Ω, 25%, 1.9A
footprint FP-BLM21-0_2-t0_85-e0_5-IPC_C
footprint FP-BLM21-0_2-t0_85-e0_5-IPC_B
footprint FP-BLM21-0_2-t0_85-e0_5-MFG
footprint FP-BLM21-0_2-t0_85-e0_5-IPC_A
pins: 1, 2

## CMP-07231-005094-1
designator R?, comment CR0603-JW-202GLF
Thick Film Chip Resistors 0603 2kΩ 0.1W 5% 200ppm/°C; Resistance: 2kR; Power Rating: 100mW; Voltage Rating: 50V
footprint FP-CR0603-IPC_B
footprint FP-CR0603-MFG
footprint FP-CR0603-IPC_C
footprint FP-CR0603-IPC_A
pins: 1, 2

## CMP-08246-000350-1
designator C?, comment 2.2pF
Cap Ceramic 2.2pF 50V C0G 0.25pF Pad SMD 0402 +125°C Automotive T/R
footprint FP-CGA2B-IPC_B
footprint FP-CGA2B-IPC_C
footprint FP-CGA2B-MFG
footprint FP-CGA2B-IPC_A
pins: 1, 2

## CMP-08246-001196-1
designator C?, comment 1nF
Cap Ceramic 1nF 250V C0G 5% Pad SMD 0603 +125°C Automotive T/R
footprint FP-CGA3E-0_3-0_1-IPC_A
footprint FP-CGA3E-0_3-0_1-IPC_B
footprint FP-CGA3E-0_3-0_1-MFG
footprint FP-CGA3E-0_3-0_1-IPC_C
pins: 1, 2

## CMP-08246-001706-1
designator C?, comment 100nF
Cap Ceramic 100nF 100V C0G 5% Pad SMD 1206 +125°C Automotive T/R
footprint FP-CGA5L-0_3-0_1-IPC_A
footprint FP-CGA5L-0_3-0_1-IPC_B
footprint FP-CGA5L-0_3-0_1-MFG
footprint FP-CGA5L-0_3-0_1-IPC_C
pins: 1, 2

## CMP-08246-001768-1
designator C?, comment 1.5pF
Cap Ceramic 1.5pF 50V C0G 0.25pF Pad SMD 0402 +125°C Automotive T/R
footprint FP-CGA2B-MFG
footprint FP-CGA2B-IPC_A
footprint FP-CGA2B-IPC_C
footprint FP-CGA2B-IPC_B
pins: 1, 2

## CMP-08246-005643-1
designator C?, comment 2.7nF
Multilayer Ceramic Capacitors 2.7nF ±5% 250V C0G SMD 0805
footprint FP-C2012-125-0_2-IPC_A
footprint FP-C2012-125-0_2-IPC_B
footprint FP-C2012-125-0_2-MFG
footprint FP-C2012-125-0_2-IPC_C
pins: 1, 2

## CMP-08246-006367-1
designator C?, comment 1.2nF
Multilayer Ceramic Capacitors 1.2nF ±5% 100V C0G SMD 0603
footprint FP-C1608-080-0_1-IPC_C
footprint FP-C1608-080-0_1-IPC_A
footprint FP-C1608-080-0_1-MFG
footprint FP-C1608-080-0_1-IPC_B
pins: 1, 2

## CMP-09082-000052-1
designator U?, comment AD5689RTCPZ-EP-RL7
IC DAC 16BIT V-OUT 16LFCSP; Min Output Voltage: 0uV; Number of DAC Channels: 2; Power Dissipation: 7.2mW; Max Supply Voltage: 5.5V; Number of Bits: 16; Resolution: 16b; Interface: SPI; Sampling Rate: 6.3MS/s; Output Type: Voltage; Operating Supply Voltage: 3V; Polarity: Unipolar; Settling Time: 5us; Integral Nonlinearity (INL): 4LSB; Signal to Noise Ratio (SNR): 90dB; Differential Output: No
footprint FP-CP-16-22-IPC_C
footprint FP-CP-16-22-IPC_B
footprint FP-CP-16-22-IPC_A
pins: 1 VOUTA, 2 GND (power), 3 VDD (power), 4 NC, 5 VOUTB, 6 SDO (out), 7 ~{LDAC} (in), 8 GAIN, 9 VLOGIC, 10 SCLK (in), 11 ~{SYNC} (in), 12 SDIN (in), 13 ~{RESET} (in), 14 RSTSEL, 15 VREF, 16 NC, 17 EPAD (power)

## CMP-09142-000059-1
designator PA?, comment ADL5320ARKZ-R7
IC RF AMP 400MHZ-2.7GHZ SOT89-3; Frequency: 400MHz; Min Supply Voltage: 3.3V; Operating Supply Voltage: 5V; Nominal Supply Current: 104mA; Gain: 13.2dB; Number of Channels: 1; P1dB: 27.4dBm; Max Frequency: 2.7GHz; Max Supply Voltage: 5.5V; Max Power Dissipation: 683mW; Noise Figure: 5.1dB; Operating Frequency: 400 MHz to 2700 MHz; Test Frequency: 2.6GHz
footprint FP-RK-3-MFG
pins: 1 RFIN, 2 GND (power), 3 RFOUT

## CMP-12153-000006-1
designator U?, comment LDL1117S33R
IC REG LINEAR 3.3V 1.2A SOT223; Manufacturer: STMicroelectronics; Output Type: Fixed; Min Supply Voltage: 2.6V; Number Of Outputs: 1; Dropout Voltage: 350mV; Output Current: 2A; Nominal Supply Current: 250uA; Standoff Height: 0.02mm; Max Supply Voltage: 18V; Max Junction Temp: +125°C; Accuracy Percentage: 2%
footprint FP-SOT223-0046067-IPC_C
footprint FP-SOT223-0046067-IPC_B
footprint FP-SOT223-0046067-IPC_A
pins: 1 GND (power), 2 VOUT (out), 3 VIN (power), 4 VOUT (out)

## CMP-26527-006412-1
designator R?, comment 0
0Ω ±0 0.1W 0603 Thick Film Chip Resistor AEC-Q200 compliant; Max Power Dissipation: 100mW; Resistance: 0R
footprint FP-RMCF0603-IPC_B
footprint FP-RMCF0603-IPC_C
footprint FP-RMCF0603-IPC_A
footprint FP-RMCF0603-MFG
pins: 1, 2

## CMP-62016-000039-1
designator D?, comment GREEN LED
LED GREEN DIFFUSED 0805 SMD; Test Current: 20mA; Power Dissipation: 65mW; Number of LEDs: 1; Viewing Angle: 160°; Lens Color: White; Lens Size: 1.25mm; Forward Voltage: 2.2V; Reverse Voltage: 12V; Forward Current: 25mA; Luminous Intensity: 45mcd; Luminous Flux: 0.1lm; Dominant Wavelength: 570nm
footprint FP-LG_R971-MFG
pins: 1 C, 2 A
